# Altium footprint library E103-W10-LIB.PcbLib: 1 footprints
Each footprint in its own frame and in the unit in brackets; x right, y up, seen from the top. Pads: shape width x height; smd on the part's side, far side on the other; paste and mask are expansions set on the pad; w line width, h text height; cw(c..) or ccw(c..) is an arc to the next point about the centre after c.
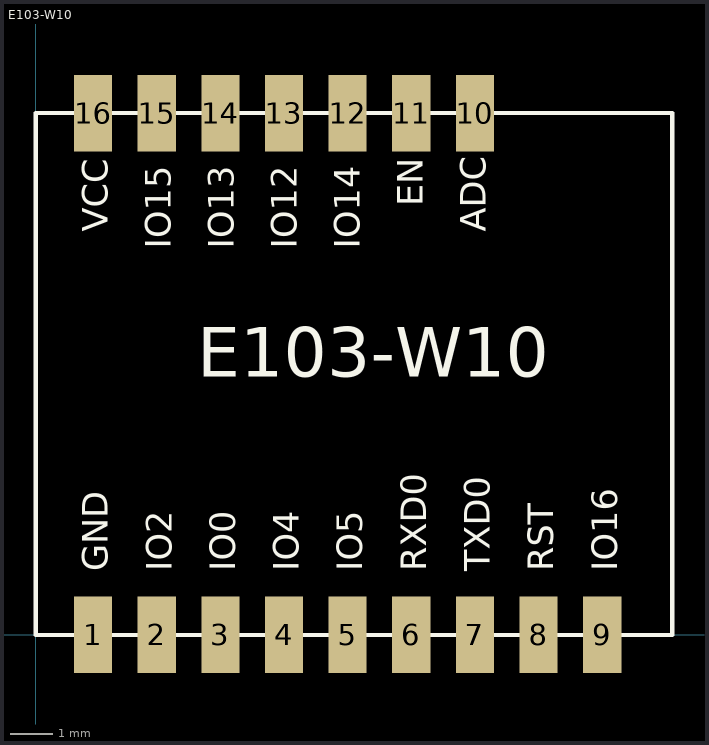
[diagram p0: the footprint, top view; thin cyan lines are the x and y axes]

## E103-W10 [mm]
pads (16):
  rect 0.9x1.8 smd: 1(1.35,0) 2(2.85,0) 3(4.35,0) 4(5.85,0) 5(7.35,0) 6(8.85,0) 7(10.35,0) 8(11.85,0) 9(13.35,0) 10(10.35,12.3) 11(8.85,12.3) 12(7.35,12.3) 13(5.85,12.3) 14(4.35,12.3) 15(2.85,12.3) 16(1.35,12.3)
Top Overlay:
  lines w0.1: 0,0 0,12.3 15,12.3 15,0 0,0
  text "VCC" at 1.7,9.5 h0.6
  text "IO15" at 3.183,9.1 h0.6
  text "IO13" at 4.667,9.1 h0.6
  text "IO12" at 6.15,9.1 h0.6
  text "IO14" at 7.633,9.1 h0.6
  text "EN" at 9.117,10.1 h0.6
  text "IO16" at 13.7,1.5 h0.6
  text "RST" at 12.2,1.5 h0.6
  text "TXD0" at 10.7,1.5 h0.6
  text "RXD0" at 9.2,1.5 h0.6
  text "IO5" at 7.7,1.5 h0.6
  text "IO4" at 6.2,1.5 h0.6
  text "IO0" at 4.7,1.5 h0.6
  text "E103-W10" at 3.8,5.7 h2
  text "ADC" at 10.6,9.5 h0.6
  text "IO2" at 3.2,1.5 h0.6
  text "GND" at 1.7,1.5 h0.6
